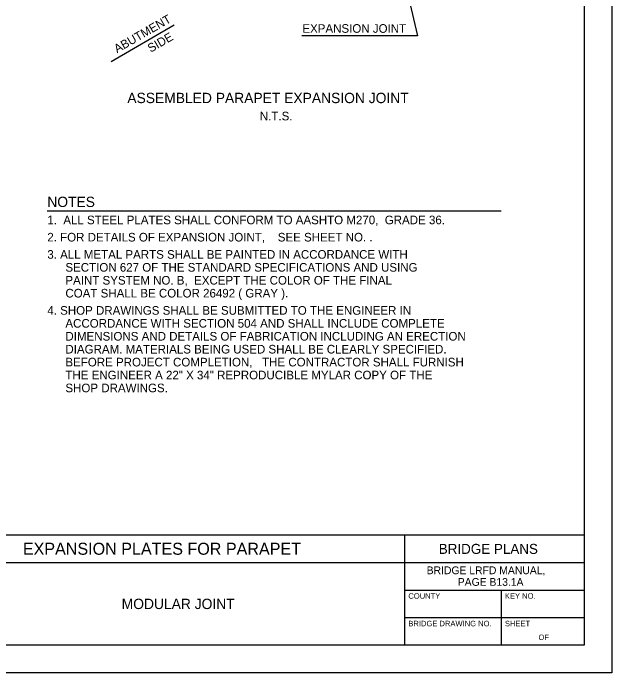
# Model space of a CAD drawing. Extents: x 0 to 22.7, y 0 to 15.7.
# Drawn here: x 15.43 to 22.67, y 0 to 7.97 of the extents above; entities that cross this region are included whole.
import ezdxf

# ---------------------------------------------------------------- set-up
doc = ezdxf.new("R2010")
doc.units = 0
for name, color, linetype in [('BORDER_ANNO_Cutsheet', 7, 'Continuous'), ('BRDG_ANNO_Anno-Sheet', 7, 'Continuous'), ('BRDG_ANNO_General-Notes', 7, 'Continuous')]:
    doc.layers.add(name, color=color, linetype=linetype)

msp = doc.modelspace()

# ---------------------------------------------------------------- linework, layer by layer
at = {"layer": 'BORDER_ANNO_Cutsheet'}
msp.add_lwpolyline([(0, 14.6667), (22.6667, 14.6667), (22.6667, 0), (0, 0)], close=True, dxfattribs=at)
at = {"layer": 'BRDG_ANNO_Anno-Sheet'}
for p, q in [((12.8333, 1.6667), (22.3333, 1.6667)), ((20.1667, 0.3333), (20.1667, 1.6667)), ((14.8333, 1.3333), (20.1667, 1.3333)), ((20.1667, 1.3333), (22.3333, 1.3333)), ((20.1667, 1), (22.3333, 1)), ((21.3333, 0.3333), (21.3333, 1)), ((20.1667, 0.6667), (22.3333, 0.6667))]:
    msp.add_line(p, q, dxfattribs=at)
msp.add_lwpolyline([(1, 14.3333), (22.3333, 14.3333), (22.3333, 0.3333), (1, 0.3333)], close=True, dxfattribs=at)
at = {"layer": 'BRDG_ANNO_General-Notes'}
for p, q in [((20.097, 8.6538), (20.3179, 7.7001)), ((16.6168, 7.3914), (17.3772, 7.8336)), ((20.3179, 7.7001), (18.9203, 7.7001)), ((21.3305, 5.5792), (15.8461, 5.5792))]:
    msp.add_line(p, q, dxfattribs=at)

# ---------------------------------------------------------------- texts
at = {"layer": 'BRDG_ANNO_Anno-Sheet'}
for s, height, p in [('EXPANSION PLATES FOR PARAPET', 0.145418, (15.5508, 1.4271)), ('BRIDGE PLANS', 0.12125, (20.5757, 1.4375)), ('BRIDGE LRFD MANUAL,', 0.09375, (20.4296, 1.1923)), ('PAGE B13.1A', 0.09375, (20.8056, 1.0517)), ('COUNTY', 0.06625, (20.2083, 0.8958)), ('KEY NO.', 0.06625, (21.375, 0.8958)), ('MODULAR JOINT', 0.125, (16.7449, 0.7708)), ('BRIDGE DRAWING NO.', 0.06625, (20.2083, 0.5625)), ('SHEET', 0.06625, (21.375, 0.5625)), ('OF', 0.06625, (21.7807, 0.3958))]:
    msp.add_text(s, height=height, dxfattribs=at).set_placement(p)
at = {"layer": 'BRDG_ANNO_General-Notes'}
for s, p in [('ABUTMENT', (16.6893, 7.4895)), ('SIDE', (17.0956, 7.4959))]:
    msp.add_text(s, height=0.10411, rotation=30.00081, dxfattribs=at).set_placement(p)
for s, height, p in [('EXPANSION JOINT', 0.104115, (18.9282, 7.7378)), ('ASSEMBLED PARAPET EXPANSION JOINT', 0.125, (16.8131, 6.8874)), ('N.T.S.', 0.10417, (18.414, 6.6791)), ('NOTES', 0.12494, (15.8461, 5.6312)), ('1.  ALL STEEL PLATES SHALL CONFORM TO AASHTO M270,  GRADE 36.', 0.104115, (15.8461, 5.4229)), ('2. FOR DETAILS OF EXPANSION JOINT,    SEE SHEET NO. .', 0.104115, (15.8461, 5.2146)), ('3. ALL METAL PARTS SHALL BE PAINTED IN ACCORDANCE WITH', 0.104115, (15.8461, 5.0062)), ('SECTION 627 OF THE STANDARD SPECIFICATIONS AND USING ', 0.104115, (16.0648, 4.85)), ('PAINT SYSTEM NO. B,  EXCEPT THE COLOR OF THE FINAL', 0.104115, (16.0648, 4.6937)), ('COAT SHALL BE COLOR 26492 ( GRAY ).', 0.104115, (16.0648, 4.5375)), ('4. SHOP DRAWINGS SHALL BE SUBMITTED TO THE ENGINEER IN', 0.104167, (15.8461, 4.3292)), ('ACCORDANCE WITH SECTION 504 AND SHALL INCLUDE COMPLETE', 0.104167, (16.0648, 4.1729)), ('DIMENSIONS AND DETAILS OF FABRICATION INCLUDING AN ERECTION', 0.104167, (16.0648, 4.0167)), ('DIAGRAM. MATERIALS BEING USED SHALL BE CLEARLY SPECIFIED.', 0.104167, (16.0648, 3.8604)), ('BEFORE PROJECT COMPLETION,   THE CONTRACTOR SHALL FURNISH', 0.104167, (16.0648, 3.7042)), ('THE ENGINEER A 22" X 34" REPRODUCIBLE MYLAR COPY OF THE', 0.104167, (16.0648, 3.5479)), ('SHOP DRAWINGS.', 0.104167, (16.0648, 3.3917))]:
    msp.add_text(s, height=height, dxfattribs=at).set_placement(p)

doc.saveas('drawing.dxf')
